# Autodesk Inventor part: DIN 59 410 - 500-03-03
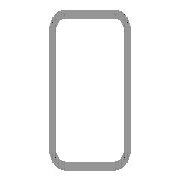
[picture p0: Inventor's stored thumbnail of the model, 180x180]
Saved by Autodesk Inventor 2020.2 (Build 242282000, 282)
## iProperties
Manager: www.cadconsulting.pl
Company: Fabian Stasiak CAD Consulting
Created: 2015-02
Part Number: DIN 59 410 - 500-03-03
Material: Stal
Description: Rurki stalowe o przekroju prostokątnym formowane na gorąco
Document SubType Name: Modellieren
Standard: DIN 59 410
Designer: F.Stasiak
Standards Organization: DIN
Language: pl-PL
Size Designation: 120x60x5-694
Categories: <MemberInstance><Categories><Category DisplayName="Kształtowniki konstrukcyjne" InternalName="089c4875-fa83-4c05-b084-43b9cc11f5ed" Mnemonic="GRDR"><CategoryPar
Stock Number: 120x60x5
Density: 7.85 g/cm^3
Appearance: Płyta
IsCustomPart: 1
G_L: 694,000 mm
Author: F.Stasiak
Subject: Zbiór ćwiczeń. Autodesk Inventor 2020. Kurs podstawowy
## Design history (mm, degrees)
node "Płaszczyzna początkowa"
node "Płaszczyzna końcowa"
sketch "Szkic1"
  geometry: L1 (-20, 60)-(20, 60); L2 (30, 50)-(30, -50); L3 (20, -60)-(-20, -60); L4 (-30, -50)-(-30, 50); L5 (-21.87, 0)-(21.87, 0) reference; L6 (0, -35.87)-(0, 35.87) reference; L7 (-20, 55)-(20, 55); L8 (25, 50)-(25, -50); L9 (20, -55)-(-20, -55); L10 (-25, -50)-(-25, 50); A1 r 10 centre (-20, 50) between (-20, 60) and (-30, 50); A2 r 10 centre (20, 50) between (30, 50) and (20, 60); A3 r 10 centre (20, -50) between (20, -60) and (30, -50); A4 r 10 centre (-20, -50) between (-30, -50) and (-20, -60); A5 r 5 centre (-20, 50) between (-20, 55) and (-25, 50); A6 r 5 centre (20, 50) between (25, 50) and (20, 55); A7 r 5 centre (20, -50) between (20, -55) and (25, -50); A8 r 5 centre (-20, -50) between (-25, -50) and (-20, -55); 3 further points
  constraints: 16 end point, 16 point on circle, 8 centre point, 8 tangent, 6 point on line, 4 parallel, 3 equal radius, 2 perpendicular, 1 horizontal, 7 other
  dimensions: "b" = 60 distance of point (-30, 60) point (30, 60); "ParH" = 120 distance of point (30, 60) point (30, -60); "msp_r" = 10 radius of A1 (= 2 x ParT); "d8" = 30 distance between parallel lines of L4 L6 (= 0.5 x b); "d9" = 60 distance between parallel lines of L5 L1 (= 0.5 x ParH); "d10" = 5 distance between parallel lines of L4 L10 (= ParT)
extrude "Bryła" new body sketch "Szkic1" taper "d4" = 0 deg; stored distance "NLG" = 10
node "Driven Length"
  sketch "Sketch2"
    geometry: L1 (0, 0)-(10, 0) reference
    constraints: 2 end point, 1 horizontal
  workplane "Work Plane3"
  sketch "Sketch3"
    geometry: L1 (-2, 0)-(12, 0) reference; L2 (-2, 694)-(12, 694) reference
    dimensions: "d14" = 694 distance between parallel lines of L1 L2 (derived)
body "Solid1"
other parameters: "ParT" = 5, "G_OFFSET_START" = 0 [user parameter; used in 1 equation term], "G_OFFSET_END" = 0 [user parameter; used in 1 equation term], "d11" = 0 (computed from G_OFFSET_START), "d12" = 694 (= G_OFFSET_END + B_L), "G_L" = 694 (= d14) [user parameter], "B_L" = 694 [user parameter; used in 1 equation term], "d13" = 90 deg
